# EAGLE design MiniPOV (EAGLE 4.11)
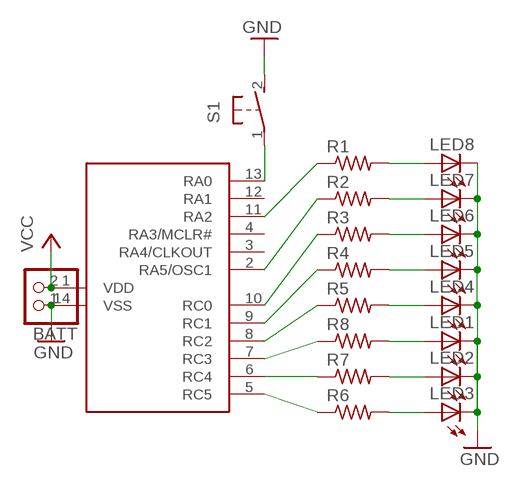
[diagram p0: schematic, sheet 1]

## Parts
BATT  PINHD-1X2  [1X02]
IC1  16F630  [DIL14]
LED1  LED5MM  [LED5MM]
LED2  LED5MM  [LED5MM]
LED3  LED5MM  [LED5MM]
LED4  LED5MM  [LED5MM]
LED5  LED5MM  [LED5MM]
LED6  LED5MM  [LED5MM]
LED7  LED5MM  [LED5MM]
LED8  LED5MM  [LED5MM]
R1  R-US_0207/2V  [0207/2V]
R2  R-US_0207/5V  [0207/5V]
R3  R-US_0207/2V  [0207/2V]
R4  R-US_0207/2V  [0207/2V]
R5  R-US_0207/2V  [0207/2V]
R6  R-US_0207/2V  [0207/2V]
R7  R-US_0207/2V  [0207/2V]
R8  R-US_0207/2V  [0207/2V]
S1  31-XX  [B3F-31XX]

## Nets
GND: BATT.1 IC1.14(VSS) LED1.K(C) LED2.K(C) LED3.K(C) LED4.K(C) LED5.K(C) LED6.K(C) LED7.K(C) LED8.K(C) S1.2(S)
N$1: IC1.10(RC0) R3.1
N$2: LED8.A R1.2
N$3: LED7.A R2.2
N$4: LED6.A R3.2
N$5: LED5.A R4.2
N$6: LED4.A R5.2
N$7: LED3.A R6.2
N$8: LED2.A R7.2
N$9: LED1.A R8.2
N$10: IC1.7(RC3) R8.1
N$11: IC1.6(RC4) R7.1
N$12: IC1.5(RC5) R6.1
N$13: IC1.8(RC2) R5.1
N$14: IC1.9(RC1) R4.1
N$15: IC1.11(RA2) R1.1
N$16: IC1.2(RA5/OSC1) R2.1
N$17: IC1.13(RA0) S1.1(P)
VDD: BATT.2 IC1.1(VDD) ; supply symbol labelled VCC
Unconnected: IC1.3(RA4/CLKOUT) IC1.4(RA3/MCLR#) IC1.12(RA1)

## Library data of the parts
BATT = pinhead:PINHD-1X2: PIN HEADER
IC1 = minipov:16F630
LED1-LED8 = led:LED: LED
R1-R8 = rcl:R-US_: RESISTOR, American symbol
S1 = switch-omron:31-XX: OMRON SWITCH

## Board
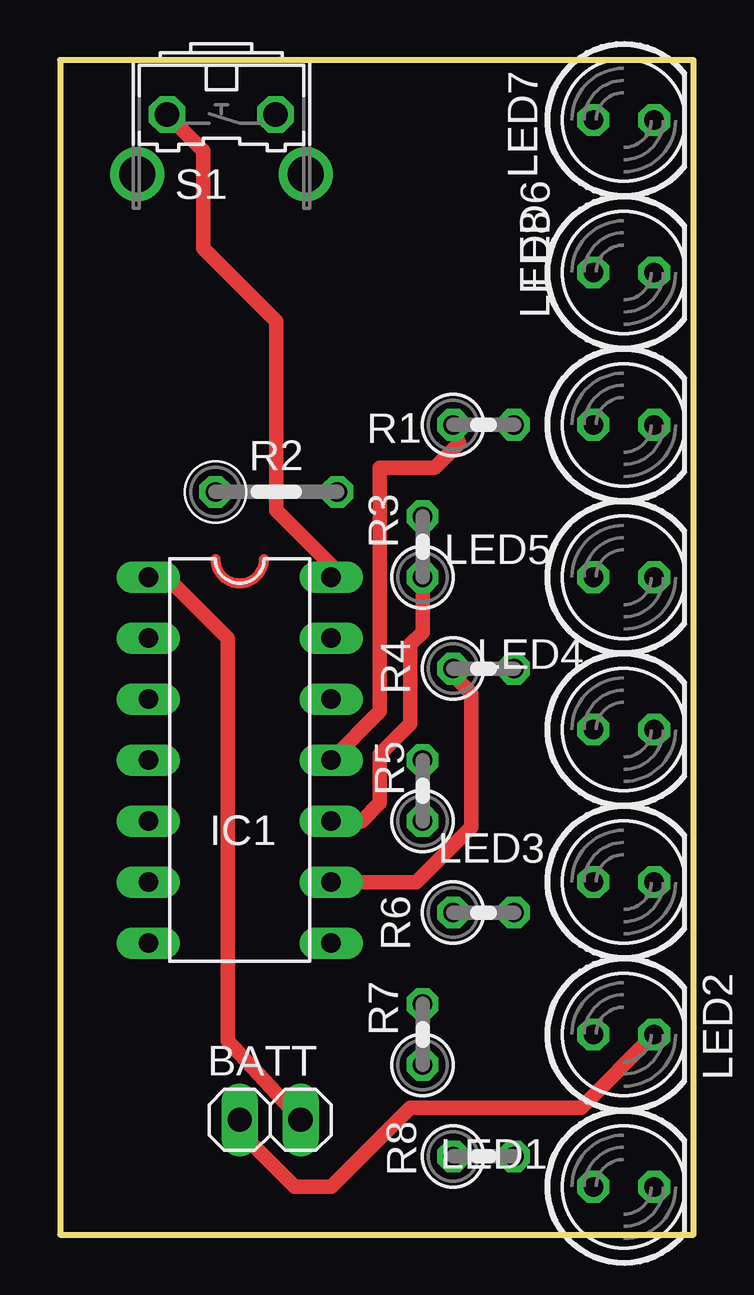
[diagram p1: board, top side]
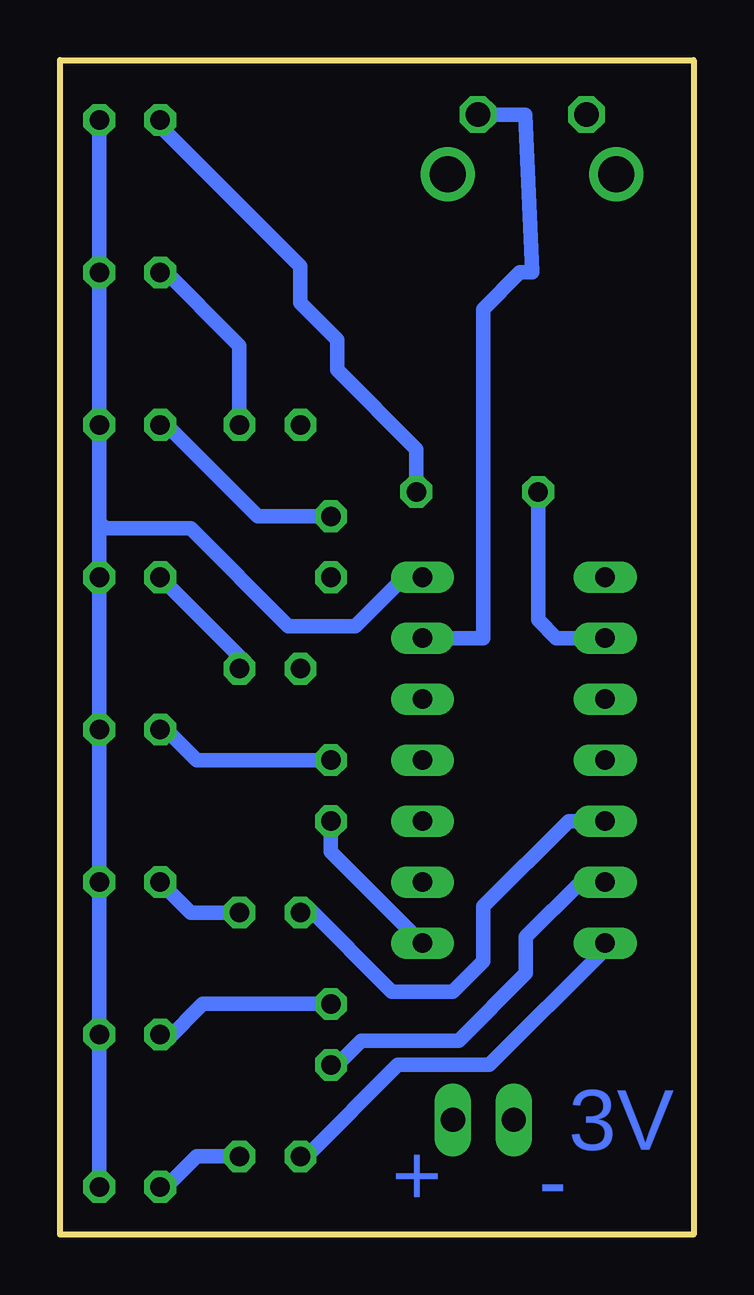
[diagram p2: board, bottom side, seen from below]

Size 26.4 x 48.95 mm. Coordinates in mm from the lower left corner, seen from the top.
Outline: 0,0 26.4,0 26.4,48.95 0,48.95 0,0
Copper layers (1*16): Top 0.035mm / dielectric 1.5mm / Bottom 0.035mm
Design rules "default": minimum track width 10mil, minimum drill 24mil, track to track 8mil, track to pad 8mil, pad to pad 8mil, via to via 8mil, smd to smd 8mil, copper to edge 40mil, drill to drill 8mil, minimum pad ring 10mil, minimum via ring 8mil, stop-mask expansion 4mil, vias tented up to drill 0mil, thermal gap 10mil

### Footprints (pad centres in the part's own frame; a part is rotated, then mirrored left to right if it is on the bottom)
1X02 = drill 1.016 long: 1 -1.27,0; 2 1.27,0
DIL14 = drill 0.813 long: 1 -7.62,-3.81; 2 -5.08,-3.81; 3 -2.54,-3.81; 4 0,-3.81; 5 2.54,-3.81; 6 5.08,-3.81; 7 7.62,-3.81; 8 7.62,3.81; 9 5.08,3.81; 10 2.54,3.81; 11 0,3.81; 12 -2.54,3.81; 13 -5.08,3.81; 14 -7.62,3.81
LED5MM = drill 0.813 octagon: A -1.27,0; K 1.27,0
0207/2V = drill 0.813 octagon: 1 -1.27,0; 2 1.27,0
0207/5V = drill 0.813 octagon: 1 -2.54,0; 2 2.54,0
B3F-31XX = drill 1.016 octagon: 1 -2.261,-1.245; 2 2.261,-1.245 | drill 1.499 pad 2.159 round: 3 -3.505,1.245; 4 3.505,1.245

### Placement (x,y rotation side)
BATT  8.76,4.79 0 top
IC1  7.49,19.77 270 top
LED1  23.49,1.99 0 top
LED2  23.49,8.34 0 top
LED3  23.49,14.69 0 top
LED4  23.49,21.04 0 top
LED5  23.49,27.39 0 top
LED6  23.49,33.74 0 top
LED7  23.49,46.44 0 top
LED8  23.49,40.09 0 top
R1  17.65,33.74 0 top
R2  9.01,30.95 0 top
R3  15.11,28.66 90 top
R4  17.65,23.58 0 top
R5  15.11,18.5 90 top
R6  17.65,13.42 0 top
R7  15.11,8.34 90 top
R8  17.65,3.26 0 top
S1  6.73,45.43 180 top

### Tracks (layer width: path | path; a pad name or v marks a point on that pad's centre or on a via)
GND
  Top 0.61: BATT.1 7.49,4.28 9.77,1.99 11.3,1.99 14.6,5.3 21.71,5.3 LED2.K | IC1.14 11.3,27.9 9.01,30.19 9.01,38.06 5.96,41.11 5.96,45.17 S1.2 4.44,46.7
  Bottom 0.61: LED7.K 24.76,40.35 24.51,40.09 LED8.K 24.76,34 25.01,33.74 LED6.K 24.76,29.68 | 24.76,29.68 24.76,27.65 24.51,27.39 LED5.K LED4.K LED3.K 24.76,8.6 24.51,8.34 LED2.K LED1.K | IC1.14 12.06,27.39 14.09,25.36 16.89,25.36 20.95,29.43 24.51,29.43 24.76,29.68
N$1
  Top 0.61: R3.1 15.11,25.11 14.6,24.6 14.6,21.3 13.33,20.03 13.33,18 12.57,17.23 IC1.10 10.79,17.23
N$2
  Bottom 0.61: LED8.A 22.22,40.35 18.92,37.05 R1.2
N$3
  Bottom 0.61: R2.2 11.55,32.73 14.85,36.03 14.85,37.3 16.38,38.82 16.38,40.35 22.22,46.19 LED7.A
N$4
  Bottom 0.61: LED6.A 21.97,33.74 18.16,29.93 R3.2
N$5
  Bottom 0.61: R4.2 18.92,24.09 LED5.A
N$6
  Bottom 0.61: LED4.A 21.97,21.04 20.7,19.77 R5.2
N$7
  Bottom 0.61: R6.2 20.95,13.42 LED3.A
N$8
  Bottom 0.61: LED2.A 21.97,8.09 20.44,9.61 R7.2
N$9
  Bottom 0.61: LED1.A 21.97,1.99 20.7,3.26 R8.2
N$10
  Bottom 0.61: IC1.7 3.68,11.9 8.5,7.07 12.31,7.07 16.12,3.26 R8.1
N$11
  Bottom 0.61: 3.42,14.95 IC1.6 4.69,14.69 6.98,12.41 6.98,10.88 9.77,8.09 13.84,8.09 14.85,7.07 R7.1
N$12
  Bottom 0.61: IC1.5 5.2,17.23 8.76,13.68 8.76,11.39 10.03,10.12 12.57,10.12 16.12,13.68 R6.1
N$13
  Bottom 0.61: R5.1 15.11,15.96 IC1.8
N$14
  Top 0.61: IC1.9 14.85,14.69 17.14,16.98 17.14,22.57 16.12,23.58 R4.1
N$15
  Top 0.61: R1.1 16.63,32.98 15.62,31.97 13.33,31.97 13.33,21.81 IC1.11
N$16
  Bottom 0.61: R2.1 6.47,25.62 5.71,24.85 IC1.2
N$17
  Bottom 0.61: S1.1 7,46.67 6.73,40.09 7.23,40.09 8.76,38.57 8.76,24.85 IC1.13
N$18
  Top 0.406: 6.47,28.16 arc180 8.5,28.16
VDD
  Top 0.61: IC1.1 4.44,27.39 6.98,24.85 6.98,8.09 BATT.2

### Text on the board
Bottom: 3V | - | +
tDocu: - | +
